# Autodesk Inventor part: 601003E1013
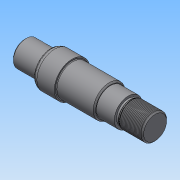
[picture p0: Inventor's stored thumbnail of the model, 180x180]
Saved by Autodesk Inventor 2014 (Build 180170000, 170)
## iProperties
Created: 2020-10
Part Number: 601003E1013
Material: 일반
Document SubType Name: Modeling
Designer: NET
Density: 1 g/cm^3
Appearance: 기본값
Author: NET
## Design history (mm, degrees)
sketch "스케치1"
  geometry: L1 (-84.656, 0)-(84.656, 0); L2 (-52, 0)-(-52, 10); L3 (-52, 10)-(-32, 10); L4 (-32, 10)-(-32, 14); L5 (-32, 14)-(-15, 14); L6 (-15, 14)-(-15, 12.5); L7 (-15, 12.5)-(15, 12.5); L8 (15, 12.5)-(15, 11); L9 (15, 11)-(29, 11); L10 (29, 11)-(29, 9.2); L11 (29, 9.2)-(30.6, 9.2); L12 (30.6, 9.2)-(31.986, 10); L13 (31.986, 10)-(50, 10); L14 (50, 10)-(50, 0); 3 further points
  constraints: 28 end point, 9 parallel, 2 coincident, 2 midpoint, 2 perpendicular, 2 point on line, 1 collinear, 1 horizontal, 1 vertical alignment
  dimensions: "d0" = 20 diameter of L3 L1; "d1" = 20 distance of L2.end L3.end; "d2" = 28 diameter of L5 L1; "d3" = 17 distance of L4.end L5.end; "d4" = 25 diameter of L7 L1; "d5" = 30 distance of L6.end L7.end; "d6" = 22 diameter of L9 L1; "d7" = 14 distance of L8.end L9.end; "d8" = 20 diameter of L13 L1; "d9" = 21 distance between parallel lines of L14 L10; "d10" = 1.6 distance of L10.end L11.end; "d11" = 18.4 diameter of L11 L1; "d12" = 150 deg angle of L11 L12
revolve "회전1" sketch "스케치1" stored, may be unused: angle "d13" = 90 deg
chamfer "모따기1" distance "d14" = 1; stored, may be unused: second distance "d15" = 2, angle "d16" = 45 deg
fillet "모깎기1" dims "d17" = 0.6
node "작업 평면1"
sketch "스케치2"
  geometry: L1 (10.729, 0)-(-1, 0); L2 (10, -3)-(-1, -3); L3 (-1, 3)-(10, 3); L4 (-10, 14)-(-10, -14) reference; L5 (10, 9)-(10, -9) reference; A1 r 3 centre (-1, 0) between (-1, 3) and (-1, -3); 3 further points
  constraints: 8 end point, 3 point on circle, 2 horizontal alignment, 2 point on line, 2 tangent, 1 centre point, 1 horizontal, 1 midpoint, 1 parallel
  dimensions: "d18" = 3 radius of A1; "d19" = 6 distance from line of point (-4, 0) L4
extrude "돌출1" cut sketch "스케치2" distance "d20" = 3.5; taper "d21" = 0 deg
fillet "모깎기2" dims "d22" = 0.6
chamfer "모따기2" distance "d23" = 1.35; stored, may be unused: second distance "d24" = 2, angle "d25" = 60 deg
fillet "모깎기3" dims "d26" = 4
fillet "모깎기4" dims "d27" = 1
feature "스레드1" dims "d28" = 10, "d29" = 0
chamfer "모따기3" distance "d30" = 1; stored, may be unused: second distance "d31" = 2, angle "d32" = 45 deg
node "솔리드1"
